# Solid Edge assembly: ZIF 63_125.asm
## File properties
Title: Zylinder
Author: bmolnar
Template: iso metric assembly.asm
Last saved by: psaghy
Revision: 26
Application: Solid Edge
Username: bmolnar
Dokumentum tartalom típus: 1
Document Number: ZIF 63/125
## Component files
Kolbenstange.par
Kit_1.par
Kit_2.par
Profilrohr.par
Mutter.par
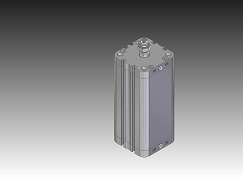
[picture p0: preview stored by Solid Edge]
